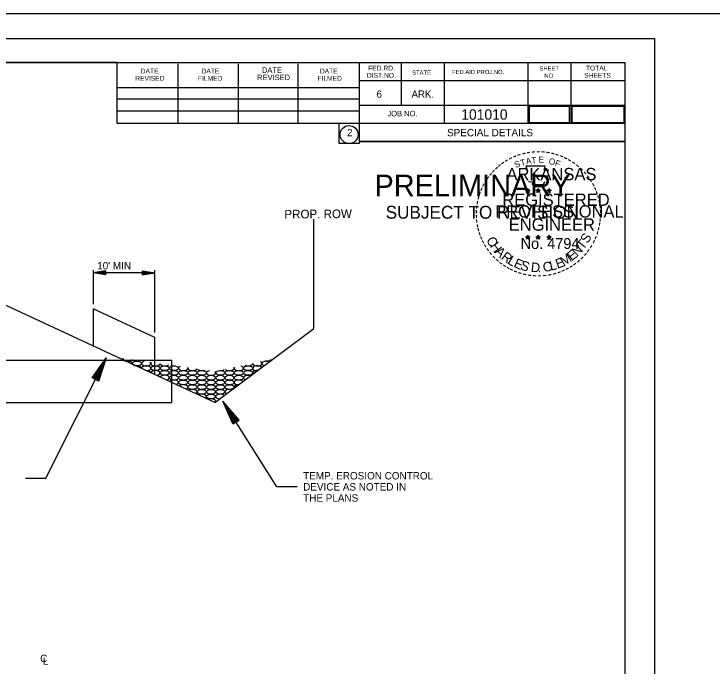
# Model space of a CAD drawing. Extents: x 3575 to 11445, y 9479 to 13278.
# Drawn here: x 6971 to 7536, y 10578 to 11106 of the extents above; entities that cross this region are included whole.
import ezdxf

# ---------------------------------------------------------------- set-up
doc = ezdxf.new("R2010")
doc.units = 0
for name, color, linetype in [('_Drafting 1', 7, 'Continuous'), ('Agg Base Course Text', 7, 'Continuous'), ('Aggregate Base Course', 7, 'Continuous'), ('CL Construction', 7, 'Continuous'), ('Default', 7, 'Continuous'), ('Page Number', 7, 'Continuous'), ('R_Culvert', 7, 'Continuous'), ('R_Dimension', 7, 'Continuous'), ('R_NoPlot', 7, 'Continuous'), ('R_ROW', 7, 'Continuous'), ('R_ROW Annot Labels', 7, 'Continuous'), ('STAMP_PE_CRAFTON-SIGNATURE', 7, 'Continuous'), ('STAMP_PE_FOSTER-SIGNATURE', 7, 'Continuous'), ('STAMP_PE_SEAL-INFO', 7, 'Continuous'), ('STAMP_PE_TAEGTMEYER', 7, 'Continuous'), ('STAMP_PRELIMINARY', 7, 'Continuous'), ('Total_Pages', 7, 'Continuous')]:
    doc.layers.add(name, color=color, linetype=linetype)

msp = doc.modelspace()

# ---------------------------------------------------------------- linework, layer by layer
at = {"layer": '_Drafting 1'}
msp.add_lwpolyline([(5884.86, 11066.7), (5884.86, 10039.4), (7465.76, 10039.4), (7465.76, 11002.7), (7250.26, 11002.7), (7250.26, 11001.26), (7234.07, 11001.26), (7234.07, 11017.3), (7054.46, 11017.3), (7054.46, 11066.7)], close=True, dxfattribs=at)
at = {"layer": 'Agg Base Course Text'}
for points in [[(6980.2, 10730.01), (6996.66, 10730.01), (7045.84, 10827.81)], [(7200.12, 10723.03), (7183.67, 10723.03), (7139.91, 10792.51)]]:
    msp.add_lwpolyline(points, dxfattribs=at)
at = {"layer": 'Aggregate Base Course'}
for centre, start_param, end_param in [((7062.91, 10826.77), 2.961843, 5.914404), ((7055.41, 10826.77), 5.909769, 6.472665), ((7062.91, 10822.95), 6.058423, 8.173848), ((7070.41, 10826.77), 3.556697, 5.31955), ((7077.91, 10822.95), 2.023003, 6.853244), ((7167.91, 10822.95), 3.156053, 7.056339), ((7175.41, 10822.95), 0.931506, 4.157324), ((7175.41, 10826.77), 4.323731, 5.962124), ((7182.91, 10826.77), 3.442076, 3.606407), ((7070.41, 10819.12), 6.220875, 8.011395), ((7077.91, 10819.12), 4.741431, 9.49084), ((7085.41, 10822.95), 2.659998, 6.216249), ((7092.91, 10822.95), 3.209812, 5.666435), ((7100.41, 10822.95), 3.937961, 4.938286), ((7107.91, 10819.12), 2.336706, 6.539541), ((7115.41, 10819.12), 2.902942, 5.973306), ((7122.91, 10819.12), 3.482724, 5.393523), ((7145.41, 10819.12), 3.620533, 6.59186), ((7152.91, 10819.12), 2.784376, 7.428017), ((7160.41, 10822.95), 3.943759, 6.268633), ((7167.91, 10819.12), 0.365489, 4.723341), ((7077.91, 10815.3), 0.125105, 1.540794), ((7085.41, 10815.3), 4.919689, 9.312581), ((7085.41, 10811.47), 0.368827, 1.297073), ((7092.91, 10811.47), 5.077258, 9.155012), ((7130.41, 10815.3), 1.929473, 6.946774), ((7137.91, 10819.12), 4.556049, 5.656343), ((7160.41, 10811.47), 0.997675, 4.091155), ((7167.91, 10815.3), 1.559925, 3.528905), ((7100.41, 10807.65), 5.223064, 9.009206), ((7152.91, 10807.65), 0.444029, 4.644801), ((7107.91, 10803.82), 5.362038, 8.870232), ((7115.41, 10800), 5.497494, 8.734776), ((7145.41, 10800), 1.06395, 4.02488), ((7152.91, 10803.82), 1.64165, 3.44718), ((7122.91, 10796.17), 5.632071, 8.6002), ((7137.91, 10796.17), 0.519106, 4.569724), ((7130.41, 10792.35), 5.839893, 8.464017)]:
    msp.add_ellipse(centre, major_axis=(3.75, 0), ratio=0.51, start_param=start_param, end_param=end_param, dxfattribs=at)
for centre in [(7070.41, 10822.95), (7085.41, 10819.12), (7092.91, 10819.12), (7100.41, 10819.12), (7160.41, 10819.12), (7092.91, 10815.3), (7100.41, 10815.3), (7100.41, 10811.47), (7107.91, 10815.3), (7107.91, 10811.47), (7115.41, 10815.3), (7115.41, 10811.47), (7122.91, 10815.3), (7122.91, 10811.47), (7130.41, 10811.47), (7137.91, 10815.3), (7137.91, 10811.47), (7145.41, 10815.3), (7145.41, 10811.47), (7152.91, 10815.3), (7152.91, 10811.47), (7160.41, 10815.3), (7107.91, 10807.65), (7115.41, 10807.65), (7122.91, 10807.65), (7130.41, 10807.65), (7137.91, 10807.65), (7145.41, 10807.65), (7115.41, 10803.82), (7122.91, 10803.82), (7122.91, 10800), (7130.41, 10803.82), (7130.41, 10800), (7137.91, 10803.82), (7137.91, 10800), (7145.41, 10803.82), (7130.41, 10796.17)]:
    msp.add_ellipse(centre, major_axis=(3.75, 0), ratio=0.51, dxfattribs=at)
at = {"layer": 'Default'}
for p, q in [((7133.59, 10791.42), (6954.56, 10874.45)), ((7035.02, 10867.13), (7035.02, 10837.13)), ((7133.59, 10791.42), (7213.59, 10851.42))]:
    msp.add_line(p, q, dxfattribs=at)
msp.add_lwpolyline([(7084.83, 10814.03), (7084.83, 10844.03), (7035.02, 10867.13)], dxfattribs=at)
at = {"layer": 'Page Number'}
msp.add_lwpolyline([(7388.08, 11018.05), (7420.73, 11018.05), (7420.73, 11031.25), (7388.08, 11031.25)], close=True, dxfattribs=at)
at = {"layer": 'R_Culvert'}
msp.add_lwpolyline([(6585.61, 10791.42), (7098.59, 10791.42), (7098.59, 10825.31), (6585.61, 10825.31)], close=True, dxfattribs=at)
at = {"layer": 'R_Dimension'}
for p, q in [((7035.02, 10898.66), (7035.02, 10871.13)), ((7045.02, 10897.89), (7035.02, 10896.39)), ((7045.02, 10897.64), (7036.69, 10896.39)), ((7045.02, 10897.89), (7045.02, 10894.89)), ((7074.83, 10897.89), (7084.83, 10896.39)), ((7074.83, 10894.89), (7074.83, 10897.89)), ((7074.83, 10897.64), (7083.16, 10896.39)), ((7084.83, 10848.04), (7084.83, 10898.66)), ((7084.83, 10896.39), (7035.02, 10896.39)), ((7045.02, 10894.89), (7035.02, 10896.39)), ((7045.02, 10895.14), (7036.69, 10896.39)), ((7045.02, 10897.39), (7038.41, 10896.39)), ((7045.02, 10895.4), (7038.41, 10896.39)), ((7045.02, 10897.14), (7040.08, 10896.39)), ((7045.02, 10895.65), (7040.08, 10896.39)), ((7045.02, 10896.88), (7041.77, 10896.39)), ((7045.02, 10895.9), (7041.77, 10896.39)), ((7045.02, 10896.63), (7043.44, 10896.39)), ((7045.02, 10896.16), (7043.44, 10896.39)), ((7074.83, 10897.39), (7081.44, 10896.39)), ((7074.83, 10897.14), (7079.77, 10896.39)), ((7074.83, 10896.88), (7078.08, 10896.39)), ((7074.83, 10896.63), (7076.41, 10896.39)), ((7074.83, 10894.89), (7084.83, 10896.39)), ((7074.83, 10895.91), (7078.08, 10896.39)), ((7074.83, 10895.4), (7081.44, 10896.39)), ((7074.83, 10895.14), (7083.16, 10896.39)), ((7074.83, 10895.65), (7079.77, 10896.39)), ((7074.83, 10896.16), (7076.41, 10896.39))]:
    msp.add_line(p, q, dxfattribs=at)
at = {"layer": 'R_NoPlot'}
msp.add_lwpolyline([(5822.82, 11086.17), (7489.52, 11086.17), (7489.52, 10019.49), (5822.82, 10019.49)], close=True, dxfattribs=at)
at = {"layer": 'R_ROW'}
msp.add_line((7213.59, 10851.44), (7213.59, 10939.74), dxfattribs=at)
at = {"layer": 'STAMP_PE_CRAFTON-SIGNATURE'}
for p, q in [((7034.17, 10811.29), (7045.84, 10827.81)), ((7034.62, 10811.06), (7044.34, 10824.83)), ((7039.09, 10808.82), (7044.34, 10824.83)), ((7039.53, 10808.59), (7045.84, 10827.81)), ((7035.07, 10810.84), (7042.79, 10821.75)), ((7035.52, 10810.61), (7041.3, 10818.78)), ((7038.18, 10809.27), (7041.3, 10818.78)), ((7038.63, 10809.05), (7042.79, 10821.75)), ((7035.98, 10810.38), (7039.77, 10815.75)), ((7037.72, 10809.51), (7039.77, 10815.75)), ((7039.53, 10808.59), (7034.17, 10811.29)), ((7036.43, 10810.15), (7038.27, 10812.76)), ((7037.27, 10809.73), (7038.27, 10812.76)), ((7148.03, 10773.99), (7139.91, 10792.51)), ((7153.11, 10777.18), (7139.91, 10792.51)), ((7148.45, 10774.25), (7141.69, 10789.68)), ((7152.68, 10776.92), (7141.69, 10789.68)), ((7152.25, 10776.65), (7143.52, 10786.77)), ((7148.88, 10774.52), (7143.52, 10786.77)), ((7149.31, 10774.79), (7145.3, 10783.95)), ((7151.83, 10776.38), (7145.3, 10783.95)), ((7151.4, 10776.11), (7147.1, 10781.09)), ((7149.75, 10775.07), (7147.1, 10781.09)), ((7148.03, 10773.99), (7153.11, 10777.18)), ((7150.97, 10775.84), (7148.88, 10778.26)), ((7150.17, 10775.33), (7148.88, 10778.26))]:
    msp.add_line(p, q, dxfattribs=at)
at = {"layer": 'STAMP_PE_FOSTER-SIGNATURE'}
for p, q in [((7385.16, 10963.44), (7386.91, 10962.89)), ((7385.16, 10963.44), (7386.43, 10963.22)), ((7385.16, 10963.44), (7386.35, 10962.83)), ((7385.83, 10961.4), (7386.91, 10962.89)), ((7385.83, 10961.4), (7386.46, 10962.62)), ((7385.83, 10961.4), (7386.9, 10962.49)), ((7386.91, 10964.71), (7386.7, 10963.45)), ((7387.97, 10961.4), (7386.9, 10962.47)), ((7386.91, 10962.89), (7386.91, 10964.71)), ((7386.91, 10964.71), (7387.15, 10963.46)), ((7388.64, 10963.44), (7386.91, 10962.89)), ((7387.97, 10961.4), (7386.91, 10962.89)), ((7388.64, 10963.44), (7387.21, 10963.2)), ((7387.97, 10961.4), (7387.29, 10962.86)), ((7388.64, 10963.44), (7387.62, 10962.93)), ((7393.51, 10963.44), (7395.26, 10962.89)), ((7393.51, 10963.44), (7394.78, 10963.22)), ((7393.51, 10963.44), (7394.7, 10962.83)), ((7394.18, 10961.4), (7395.26, 10962.89)), ((7394.18, 10961.4), (7394.81, 10962.62)), ((7394.18, 10961.4), (7395.25, 10962.49)), ((7395.26, 10964.71), (7395.05, 10963.45)), ((7396.32, 10961.4), (7395.25, 10962.47)), ((7395.26, 10962.89), (7395.26, 10964.71)), ((7395.26, 10964.71), (7395.5, 10963.46)), ((7396.99, 10963.44), (7395.26, 10962.89)), ((7396.32, 10961.4), (7395.26, 10962.89)), ((7396.99, 10963.44), (7395.56, 10963.2)), ((7396.32, 10961.4), (7395.64, 10962.86)), ((7396.99, 10963.44), (7395.97, 10962.93)), ((7402.33, 10963.38), (7404.08, 10962.83)), ((7402.33, 10963.38), (7403.6, 10963.16)), ((7402.33, 10963.38), (7403.52, 10962.77)), ((7403, 10961.34), (7404.08, 10962.83)), ((7403, 10961.34), (7403.63, 10962.56)), ((7403, 10961.34), (7404.07, 10962.43)), ((7404.08, 10964.65), (7403.87, 10963.39)), ((7405.14, 10961.34), (7404.07, 10962.41)), ((7404.08, 10962.83), (7404.08, 10964.65)), ((7404.08, 10964.65), (7404.32, 10963.4)), ((7405.81, 10963.38), (7404.08, 10962.83)), ((7405.14, 10961.34), (7404.08, 10962.83)), ((7405.81, 10963.38), (7404.38, 10963.14)), ((7405.14, 10961.34), (7404.46, 10962.8)), ((7405.81, 10963.38), (7404.79, 10962.87)), ((7386.89, 10926.85), (7386.68, 10925.59)), ((7386.89, 10925.02), (7386.89, 10926.85)), ((7386.89, 10926.85), (7387.13, 10925.6)), ((7395.23, 10926.85), (7395.03, 10925.59)), ((7395.23, 10925.02), (7395.23, 10926.85)), ((7395.23, 10926.85), (7395.48, 10925.6)), ((7404.07, 10926.8), (7403.86, 10925.54)), ((7404.07, 10924.97), (7404.07, 10926.8)), ((7404.07, 10926.8), (7404.31, 10925.55)), ((7385.14, 10925.58), (7386.89, 10925.02)), ((7385.14, 10925.58), (7386.41, 10925.35)), ((7385.14, 10925.58), (7386.33, 10924.97)), ((7385.81, 10923.54), (7386.89, 10925.02)), ((7385.81, 10923.54), (7386.44, 10924.76)), ((7385.81, 10923.54), (7386.88, 10924.62)), ((7387.95, 10923.54), (7386.88, 10924.61)), ((7388.62, 10925.58), (7386.89, 10925.02)), ((7387.95, 10923.54), (7386.89, 10925.02)), ((7388.62, 10925.58), (7387.19, 10925.33)), ((7387.95, 10923.54), (7387.27, 10924.99)), ((7388.62, 10925.58), (7387.6, 10925.07)), ((7393.49, 10925.58), (7395.23, 10925.02)), ((7393.49, 10925.58), (7394.75, 10925.35)), ((7393.49, 10925.58), (7394.67, 10924.97)), ((7394.15, 10923.54), (7395.23, 10925.02)), ((7394.15, 10923.54), (7394.78, 10924.76)), ((7394.15, 10923.54), (7395.22, 10924.62)), ((7396.3, 10923.54), (7395.22, 10924.61)), ((7396.97, 10925.58), (7395.23, 10925.02)), ((7396.3, 10923.54), (7395.23, 10925.02)), ((7396.97, 10925.58), (7395.54, 10925.33)), ((7396.3, 10923.54), (7395.61, 10924.99)), ((7396.97, 10925.58), (7395.95, 10925.07)), ((7402.32, 10925.53), (7404.07, 10924.97)), ((7402.32, 10925.53), (7403.59, 10925.3)), ((7402.32, 10925.53), (7403.51, 10924.92)), ((7402.99, 10923.49), (7404.07, 10924.97)), ((7402.99, 10923.49), (7403.62, 10924.71)), ((7402.99, 10923.49), (7404.06, 10924.57)), ((7405.13, 10923.49), (7404.06, 10924.56)), ((7405.8, 10925.53), (7404.07, 10924.97)), ((7405.13, 10923.49), (7404.07, 10924.97)), ((7405.8, 10925.53), (7404.37, 10925.28)), ((7405.13, 10923.49), (7404.45, 10924.94)), ((7405.8, 10925.53), (7404.78, 10925.02))]:
    msp.add_line(p, q, dxfattribs=at)
for points in [[(7385.37, 10982.83), (7386.71, 10978.7)], [(7402.92, 10978.22), (7403.63, 10979.64), (7400.21, 10979.52), (7400.95, 10982.83), (7385.37, 10982.83)], [(7387.83, 10970.72), (7387.83, 10970.28), (7390.64, 10970.19), (7390.37, 10967.82), (7399.72, 10967.82), (7400.73, 10970.5)], [(7386.91, 10964.71), (7387.97, 10961.4), (7385.16, 10963.44), (7388.64, 10963.44), (7385.83, 10961.4), (7386.91, 10964.71)], [(7395.26, 10964.71), (7396.32, 10961.4), (7393.51, 10963.44), (7396.99, 10963.44), (7394.18, 10961.4), (7395.26, 10964.71)], [(7404.08, 10964.65), (7405.14, 10961.34), (7402.33, 10963.38), (7405.81, 10963.38), (7403, 10961.34), (7404.08, 10964.65)], [(7386.89, 10926.85), (7387.95, 10923.54), (7385.14, 10925.58), (7388.62, 10925.58), (7385.81, 10923.54), (7386.89, 10926.85)], [(7395.23, 10926.85), (7396.3, 10923.54), (7393.49, 10925.58), (7396.97, 10925.58), (7394.15, 10923.54), (7395.23, 10926.85)], [(7404.07, 10926.8), (7405.13, 10923.49), (7402.32, 10925.53), (7405.8, 10925.53), (7402.99, 10923.49), (7404.07, 10926.8)]]:
    msp.add_lwpolyline(points, dxfattribs=at)
for centre, radius in [((7386.9, 10962.88), 0.861), ((7386.9, 10962.88), 0.723), ((7386.9, 10962.88), 0.579), ((7386.9, 10962.88), 0.495), ((7386.9, 10962.88), 0.374), ((7386.9, 10962.88), 0.248), ((7386.9, 10962.88), 0.148), ((7395.25, 10962.88), 0.861), ((7395.25, 10962.88), 0.723), ((7395.25, 10962.88), 0.579), ((7395.25, 10962.88), 0.495), ((7395.25, 10962.88), 0.374), ((7395.25, 10962.88), 0.248), ((7395.25, 10962.88), 0.148), ((7404.07, 10962.82), 0.861), ((7404.07, 10962.82), 0.723), ((7404.07, 10962.82), 0.579), ((7404.07, 10962.82), 0.495), ((7404.07, 10962.82), 0.374), ((7404.07, 10962.82), 0.248), ((7404.07, 10962.82), 0.148), ((7386.88, 10925.02), 0.861), ((7395.23, 10925.02), 0.861), ((7386.88, 10925.02), 0.723), ((7386.88, 10925.02), 0.579), ((7386.88, 10925.02), 0.495), ((7386.88, 10925.02), 0.374), ((7386.88, 10925.02), 0.248), ((7386.88, 10925.02), 0.148), ((7395.23, 10925.02), 0.723), ((7395.23, 10925.02), 0.579), ((7395.23, 10925.02), 0.495), ((7395.23, 10925.02), 0.374), ((7395.23, 10925.02), 0.248), ((7395.23, 10925.02), 0.148), ((7404.06, 10924.97), 0.861), ((7404.06, 10924.97), 0.723), ((7404.06, 10924.97), 0.579), ((7404.06, 10924.97), 0.495), ((7404.06, 10924.97), 0.374), ((7404.06, 10924.97), 0.248), ((7404.06, 10924.97), 0.148)]:
    msp.add_circle(centre, radius, dxfattribs=at)
at = {"layer": 'STAMP_PRELIMINARY'}
for p, q in [((7488.76, 11106.1), (5728.76, 11106.1)), ((9248.58, 11106.1), (7488.58, 11106.1)), ((5884.86, 11066.7), (7465.76, 11066.7)), ((7054.46, 11017.3), (7054.46, 11066.7)), ((7103.76, 11017.3), (7103.76, 11065.7)), ((7152.56, 11017.3), (7152.56, 11065.7)), ((7200.96, 11017.3), (7200.96, 11065.7)), ((7250.26, 11066.7), (7250.26, 11002.7)), ((7284.46, 11066.7), (7284.46, 11032)), ((7319.16, 11066.7), (7319.16, 11017.3)), ((7387.06, 11066.7), (7387.06, 11017.3)), ((7421.76, 11066.7), (7421.76, 11017.3)), ((7465.76, 10039.4), (7465.76, 11066.7)), ((7465.76, 11052), (7250.26, 11052)), ((7465.76, 11052.1), (7465.76, 11052.1)), ((7054.46, 11046.6), (7250.26, 11046.6)), ((7054.46, 11037.3), (7250.26, 11037.3)), ((7054.46, 11027.6), (7250.26, 11027.6)), ((7465.76, 11032), (7250.26, 11032)), ((7465.76, 11017.3), (7054.46, 11017.3)), ((7250.26, 11002.7), (7465.76, 11002.7))]:
    msp.add_line(p, q, dxfattribs=at)
msp.add_circle((7242.19, 11008.38), 7.33, dxfattribs=at)
at = {"layer": 'Total_Pages'}
msp.add_lwpolyline([(7422.58, 11018.05), (7464.94, 11018.05), (7464.94, 11031.25), (7422.58, 11031.25)], close=True, dxfattribs=at)

# ---------------------------------------------------------------- texts
at = {"layer": 'Agg Base Course Text'}
for s, p in [('TEMP. EROSION CONTROL', (7205.03, 10729.03)), ('DEVICE AS NOTED IN ', (7205.03, 10720.03)), ('THE PLANS', (7205.03, 10711.03))]:
    msp.add_text(s, height=6, dxfattribs=at).set_placement(p)
at = {"layer": 'CL Construction'}
for s, p in [('C', (6992.04, 10581.06)), ('L', (6994.29, 10578.95))]:
    msp.add_text(s, height=6, dxfattribs=at).set_placement(p)
at = {"layer": 'R_Dimension'}
msp.add_text("10' MIN", height=6, dxfattribs=at).set_placement((7038.26, 10899.18))
at = {"layer": 'R_ROW Annot Labels'}
msp.add_text('PROP. ROW', height=7, rotation=0.435, dxfattribs=at).set_placement((7189.88, 10940.37))
at = {"layer": 'STAMP_PE_FOSTER-SIGNATURE'}
for s, height, rotation, p in [('-', 8, 13.6302, (7382.86, 10989.67)), ('-', 8, 10.2193, (7386.25, 10990.48)), ('-', 8, 5.8968, (7389.89, 10991.03)), ('-', 8, 0.1862, (7393.75, 10991.39)), ('-', 8, 357.743, (7397.37, 10991.33)), ('-', 8, 352.1617, (7401.09, 10991.05)), ('-', 8, 347.2049, (7404.68, 10990.48)), ('-', 8, 34.0636, (7369.79, 10983.69)), ('-', 8, 28.7918, (7372.77, 10985.54)), ('-', 8, 24.3072, (7375.94, 10987.12)), ('-', 8, 19.1761, (7379.11, 10988.47)), ('T', 5, 16.4036, (7381.71, 10982.88)), ('A', 5, 11.2132, (7385.84, 10984.13)), ('T', 5, 6.0228, (7390.09, 10984.96)), ('E', 5, 0.8323, (7395.61, 10985.51)), ('O', 5, 350.4515, (7403.63, 10984.46)), ('-', 8, 342.3362, (7407.86, 10989.7)), ('-', 8, 337.8551, (7411.53, 10988.59)), ('-', 8, 334.1211, (7414.69, 10987.23)), ('-', 8, 329.6409, (7417.58, 10985.82)), ('-', 8, 42.9622, (7362.35, 10977.74)), ('-', 8, 38.9507, (7364.52, 10979.82)), ('-', 8, 36.2317, (7366.9, 10981.71)), ('S', 5, 21.594, (7377.14, 10981.22)), ('F', 5, 340.0707, (7408.4, 10983.32)), ('-', 8, 325.8627, (7420.8, 10984.01)), ('-', 8, 320.5297, (7423.85, 10981.88)), ('-', 8, 50.6142, (7358.1, 10972.92)), ('-', 8, 48.4231, (7360.11, 10975.35)), ('-', 8, 315.5786, (7426.84, 10979.44)), ('-', 8, 309.8797, (7429.69, 10976.69)), ('-', 8, 58.0706, (7354.41, 10967.45)), ('-', 8, 54.2325, (7356.03, 10970.08)), ('-', 8, 306.6522, (7432.31, 10973.68)), ('-', 7, 303.6753, (7434.74, 10970.84)), ('-', 8, 67.7743, (7351.55, 10961.32)), ('-', 8, 62.8713, (7352.84, 10964.38)), ('-', 8, 299.6684, (7436.34, 10967.81)), ('-', 8, 294.6628, (7437.96, 10964.75)), ('-', 8, 72.3945, (7350.45, 10958.17)), ('-', 8, 290.5728, (7439.24, 10961.86)), ('-', 8, 81.2013, (7348.81, 10951.04)), ('-', 8, 75.461, (7349.47, 10954.6)), ('-', 8, 285.1233, (7440.41, 10958.96)), ('-', 8, 280.5493, (7441.41, 10955.25)), ('-', 8, 85.1863, (7348.43, 10947.58)), ('-', 8, 276.5962, (7442.22, 10951.41)), ('-', 8, 94.1959, (7348.48, 10940.45)), ('-', 8, 89.0622, (7348.3, 10944.08)), ('-', 8, 274.3301, (7442.52, 10947.8)), ('-', 8, 269.9407, (7442.69, 10944.64)), ('-', 8, 98.9479, (7348.84, 10937.12)), ('-', 8, 260.9953, (7442.24, 10938.04)), ('-', 8, 263.5172, (7442.6, 10941.31)), ('-', 8, 101.7149, (7349.51, 10933.45)), ('-', 8, 105.4578, (7350.32, 10930.48)), ('-', 8, 255.7626, (7441.69, 10934.65)), ('-', 8, 109.0874, (7351.4, 10927.32)), ('-', 8, 114.0643, (7352.67, 10924.34)), ('S', 7.7, 57.878, (7435.35, 10919.68)), ('-', 8, 247.8887, (7439.67, 10927.69)), ('-', 8, 255.7626, (7440.73, 10931.21)), ('-', 8, 115.7289, (7354.19, 10921.25)), ('C', 7.7, 296.9133, (7353.03, 10923.3)), ('H', 7.7, 303.2799, (7355.99, 10918.1)), ('T', 7.7, 51.5114, (7431.7, 10914.47)), ('-', 8, 244.6197, (7438.36, 10924.54)), ('-', 8, 120.4471, (7355.98, 10918.32)), ('-', 8, 125.8934, (7357.99, 10915.52)), ('A', 7.7, 316.013, (7359.63, 10912.97)), ('E', 7.7, 38.7783, (7422.46, 10905.61)), ('N', 7.7, 45.1449, (7426.9, 10909.26)), ('-', 8, 233.8452, (7434.38, 10917.52)), ('-', 8, 239.0712, (7436.39, 10920.78)), ('-', 8, 130.7181, (7360.3, 10912.76)), ('-', 8, 134.2238, (7362.89, 10910.03)), ('R', 7.7, 322.3796, (7364.75, 10908.06)), ('L', 7.7, 328.7461, (7369.89, 10904.31)), ('E', 7.7, 19.6786, (7410.94, 10899.66)), ('M', 7.7, 32.4117, (7416.06, 10901.55)), ('-', 8, 225.7653, (7429.84, 10911.87)), ('-', 8, 231.2538, (7432.23, 10914.69)), ('-', 8, 138.9338, (7365.51, 10907.71)), ('-', 8, 144.6463, (7368.29, 10905.68)), ('E', 7.7, 335.1127, (7374.91, 10901.52)), ('S', 7.7, 341.4792, (7380.24, 10899.36)), ('D', 7.7, 354.2124, (7389.08, 10897.3)), ('C', 7.7, 6.9455, (7399.51, 10897.11)), ('L', 7.7, 13.3121, (7405.43, 10898.06)), ('-', 8, 215.7363, (7424.48, 10906.96)), ('-', 8, 221.0851, (7427.23, 10909.32)), ('-', 8, 148.0898, (7371.1, 10903.83)), ('-', 8, 151.5704, (7373.99, 10902.2)), ('-', 8, 154.6002, (7376.6, 10900.97)), ('-', 8, 158.5612, (7379.72, 10899.7)), ('.', 7.7, 0.5789, (7394.94, 10896.92)), ('-', 8, 200.7184, (7412.81, 10900.34)), ('-', 8, 204.2516, (7415.9, 10901.7)), ('-', 8, 207.3568, (7419.02, 10903.3)), ('-', 8, 212.2491, (7421.81, 10905.03)), ('-', 8, 162.7983, (7383.16, 10898.63)), ('-', 8, 167.5555, (7386.73, 10897.81)), ('-', 8, 173.1155, (7390.59, 10897.26)), ('-', 8, 176.5183, (7394.33, 10897)), ('-', 8, 181.5918, (7398.05, 10897.09)), ('-', 8, 185.8167, (7402.1, 10897.47)), ('-', 8, 191.2858, (7405.78, 10898.13)), ('-', 8, 195.4743, (7409.42, 10899.13))]:
    msp.add_text(s, height=height, rotation=rotation, dxfattribs=at).set_placement(p)
for s, height, p in [('ARKANSAS', 10, (7369.63, 10971.39)), ('REGISTERED', 10, (7366.24, 10950.65)), ('PROFESSIONAL', 10, (7360.5, 10941.13)), ('ENGINEER', 10, (7371.44, 10930.5)), ('No. 4794', 8.785, (7381.06, 10915.75))]:
    msp.add_text(s, height=height, dxfattribs=at).set_placement(p)
at = {"layer": 'STAMP_PE_SEAL-INFO'}
for s, height, p in [('PRELIMINARY', 17.5, (7262.79, 10958.41)), ('SUBJECT TO REVISION', 10.3756, (7271.83, 10940.26))]:
    msp.add_text(s, height=height, dxfattribs=at).set_placement(p)
at = {"layer": 'STAMP_PE_TAEGTMEYER'}
for s, height, p in [('101010', 8.4, (7333.03, 11020.45)), ('SPECIAL DETAILS', 6, (7321.52, 11007))]:
    msp.add_text(s, height=height, dxfattribs=at).set_placement(p)
at = {"layer": 'STAMP_PRELIMINARY'}
for s, height, p in [('DATE', 3.91, (7073.46, 11057.9)), ('DATE', 3.91, (7122.76, 11057.9)), ('DATE', 4.396, (7171.66, 11058.4)), ('DATE', 3.91, (7218.56, 11057.9)), ('FED.RD.', 3.91, (7257.66, 11060.3)), ('SHEET', 3.42, (7396.36, 11060.3)), ('TOTAL', 3.91, (7433.96, 11060.3)), ('REVISED', 3.91, (7069.06, 11052)), ('FILMED', 3.91, (7119.86, 11052)), ('REVISED', 4.396, (7167.76, 11052.5)), ('FILMED', 3.91, (7216.56, 11052)), ('DIST.NO.', 3.91, (7256.66, 11054.4)), ('STATE', 3.42, (7293.26, 11056.9)), ('FED.AID PROJ.NO.', 3.42, (7325.56, 11057.4)), ('NO.', 3.42, (7400.26, 11054.4)), ('SHEETS', 3.91, (7432.56, 11054.4)), ('6', 5.86, (7264.46, 11038.3)), ('ARK.', 5.861, (7292.76, 11038.3)), ('JOB NO.', 4.396, (7273.26, 11023.2)), ('2', 5.86, (7240.56, 11007.1))]:
    msp.add_text(s, height=height, dxfattribs=at).set_placement(p)

doc.saveas('drawing.dxf')
